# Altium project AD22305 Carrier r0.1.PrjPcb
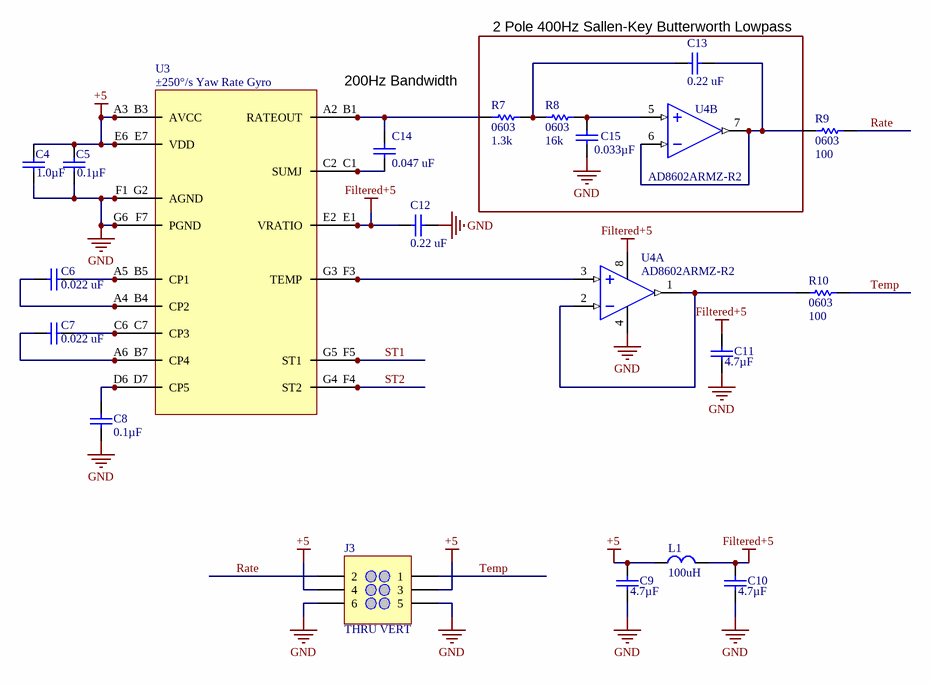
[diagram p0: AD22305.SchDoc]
ProjectTitle: AD22305 Carrier r0.1
2 sheets, 20 parts. Net scope: global (net labels, ports and power ports of the same name join across sheets).
Board file: AD22305 Carrier.PcbDoc
Sheets:
  AD22305.SchDoc
  Title.SchDoc

## Sheet AD22305.SchDoc
size Letter; SheetNumber: 2; SheetTotal: 2

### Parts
C4  value 1.0µF  [C0805_C]  (hidden comment: 1.0 uF 0805  25V)
C5  value 0.1µF  [C0805_C]  (hidden comment: 0.1uF 0805 Bypass)
C6  value 0.022 uF  [C0603_C]  (hidden comment: 0.022 uF 0603)
C7  value 0.022 uF  [C0603_C]  (hidden comment: 0.022 uF 0603)
C8  value 0.1µF  [C0805_C]  (hidden comment: 0.1uF 0805 Bypass)
C9  value 4.7µF  [C0805_C]  (hidden comment: 4.7uF 0805 25V X5R)
C10  value 4.7µF  [C0805_C]  (hidden comment: 4.7uF 0805 25V X5R)
C11  value 4.7µF  [C0805_C]  (hidden comment: 4.7uF 0805 25V X5R)
C12  value 0.22 uF  [C0603_C]  (hidden comment: 0.22 uF 0603)
C13  value 0.22 uF  [C0603_C]  (hidden comment: 0.22 uF 0603)
C14  value 0.047 uF  [C0603_C]  (hidden comment: 0.047uF 0603)
C15  value 0.033µF  [C0603_C]  (hidden comment: 0.022 uF 0603)
J3  THRU VERT  [H100P2x3 TSW-103-07-T-D]
L1  value 100uH  [L0805_C]  (hidden comment: 100 uH)
R7  value 1.3k  Footprint: 0603  [R0603_C]  (hidden comment: 1.3k ohm 0603 1%)
R8  value 16k  Footprint: 0603  [R0603_C]  (hidden comment: 16k ohm 0603 1%)
R9  value 100  Footprint: 0603  [R0603_C]  (hidden comment: 100 ohm 0603 1%)
R10  value 100  Footprint: 0603  [R0603_C]  (hidden comment: 100 ohm 0603 1%)
U3  ±250°/s Yaw Rate Gyro  [BC-32]
U4  MFG_PN: AD8602ARMZ-R2  [RM-8]  (hidden comment: AD8602 TSSOP)  (parts A,B of 2)

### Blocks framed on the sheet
2 Pole 400Hz Sallen-Key Butterworth Lowpass: C13 C15 R7 R8 U4

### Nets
+5: C4.2 C5.2 C9.2 J3.3 J3.4 L1.1 U3.A3(AVCC) U3.B3(AVCC) U3.E6(VDD) U3.E7(VDD)
Filtered+5: C10.2 C11.2 C12.2 L1.2 U3.E1(VRATIO) U3.E2(VRATIO) U4.8(+V)
GND: C4.1 C5.1 C8.1 C9.1 C10.1 C11.1 C12.1 C15.1 J3.5 J3.6 U3.F1(AGND) U3.F7(PGND) U3.G2(AGND) U3.G6(PGND) U4.4(-V)
Rate: J3.2 R9.2
ST1: U3.F5(ST1) U3.G5(ST1)
ST2: U3.F4(ST2) U3.G4(ST2)
Temp: J3.1 R10.2
NetC6_1: C6.1 U3.A4(CP2) U3.B4(CP2)
NetC6_2: C6.2 U3.A5(CP1) U3.B5(CP1)
NetC7_1: C7.1 U3.A6(CP4) U3.B7(CP4)
NetC7_2: C7.2 U3.C6(CP3) U3.C7(CP3)
NetC8_2: C8.2 U3.D6(CP5) U3.D7(CP5)
NetC13_1: C13.1 R9.1 U4.6(-IN_B) U4.7(OUT_B)
NetC13_2: C13.2 R7.2 R8.1
NetC14_1: C14.1 U3.C1(SUMJ) U3.C2(SUMJ)
NetC14_2: C14.2 R7.1 U3.A2(RATEOUT) U3.B1(RATEOUT)
NetC15_2: C15.2 R8.2 U4.5(+IN_B)
NetR10_1: R10.1 U4.1(OUT_A) U4.2(-IN_A)
NetU3_F3: U3.F3(TEMP) U3.G3(TEMP) U4.3(+IN_A)

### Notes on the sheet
- 200Hz Bandwidth

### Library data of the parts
C4 = 1.0 uF 0805  25V: MFG: Panasonic - ECG; MFG_PN: ECJ-2FB1E105K; DIST: DigiKey; DIST_PN: PCC2319CT-ND; Tolerance: ±10%; Temperature Coefficient: X5R; Voltage: 25
C5 C8 = 0.1uF 0805 Bypass: MFG: Kemet; MFG_PN: C0805C104K5RACTU; DIST: DigiKey; DIST_PN: 399-1170-1-ND; Tolerance: ±10%; Temperature Coefficient: X7R; Voltage: 50; Checked: SCH 3/2/2008; Cost (1000): 0.01260
C6 C7 = 0.022 uF 0603 50V: MFG: Panasonic - ECG; MFG_PN: ECJ-1VB1H223K; DIST: DigiKey; DIST_PN: PCC2282CT-ND; Tolerance: ±10%; Temperature Coefficient: X7R; Voltage: 50
C9-C11 = 4.7uF 0805 25V X5R: CERAMIC 4.7uF 25V X5R 0805; MFG: Panasonic - ECG; MFG_PN: ECJ-2FB1E475M; DIST: DigiKey; DIST_PN: PCC2321CT-ND; Tolerance: ±20%; Voltage: 25; Checked: SCH 3/2/2008; Cost (1000): 0.08988
C12 C13 = 0.22 uF 0603 10V: Capacitor; MFG: Panasonic - ECG; MFG_PN: ECJ-1VB1A224K; DIST: DigiKey; DIST_PN: PCC1749CT-ND; Tolerance: 10%; Temperature Coefficient: X5R; Voltage: 10
C14 = 0.047 uF 0603 50V: Capacitor; MFG: Panasonic - ECG; MFG_PN: ECJ-1VF1H473Z; DIST: DigiKey; DIST_PN: PCC1805CT-ND; Tolerance: -20%, +80%; Temperature Coefficient: Y5V (F); Voltage: 50
C15 = 0.033µF 0603 25V: MFG: Murata Electronics North America; MFG_PN: GRM188R71E333KA01D; DIST: DigiKey; DIST_PN: 490-1521-1-ND; Tolerance: ±10%; Temperature Coefficient: X7R; Voltage: 25; Cost (1000): 0.01300; Cost (MOQ): 0.05500
J3 = H100 2x3 THRU VERT: 2x3 Bird Pins; DIST: Samtec; DIST_PN: TSW-103-07-T-D; Cost (1000): 0.188; Cost (MOQ): 0.220; BOM Note: Generic
L1 = 100 uH 0805: MFG: Taiyo Yuden; MFG_PN: LBR2012T101K; DIST: DigiKey; DIST_PN: 587-2048-1-ND; Tol: 10%; Current Max: 0.050; Cost (1000): 0.06250
R7 = 1.3k ohm 0603 1%: MFG: Rohm; MFG_PN: MCR03EZPFX1301; DIST: DigiKey; DIST_PN: RHM1.30KHCT-ND; Power: 0.1; Cost (1000): 0.01595; Cost (MOQ): 0.076; BOM Note: Generic - May be replaced by equal or better part
R8 = 16k ohm 0603 1%: MFG: Rohm; MFG_PN: MCR03EZPFX1602; DIST: DigiKey; DIST_PN: RHM16.0KHCT-ND; Power: 0.1; Cost (1000): 0.01595; Cost (MOQ): 0.076; BOM Note: Generic - May be replaced by equal or better part
R9 R10 = 100 ohm 0603 1%: MFG: Rohm; MFG_PN: MCR03EZPFX1000; DIST: DigiKey; DIST_PN: RHM100HCT-ND; Power: 0.1; Cost (1000): 0.01595; Cost (MOQ): 0.076; BOM Note: Generic - May be replaced by equal or better part
U3 = AD22305: Supply Voltage Range: 4.85 - 5.15
U4 = AD8602 TSSOP: Op Amp 2x 8MHz Rail to Rail; DIST: DigiKey; DIST_PN: AD8602ARMZ-R2CT-ND; Maximum Output Current: 0.050; MFG: Analog Devices Inc; Noise, nV/rt(Hz): 8; Offset Voltage, Max (mV): 6; Offset Voltage, Nom (mV): 1.1; Cost (MOQ): 2.28000; Cost (1000): 1.36500

## Sheet Title.SchDoc
size Letter; SheetNumber: 0; SheetTotal: 2
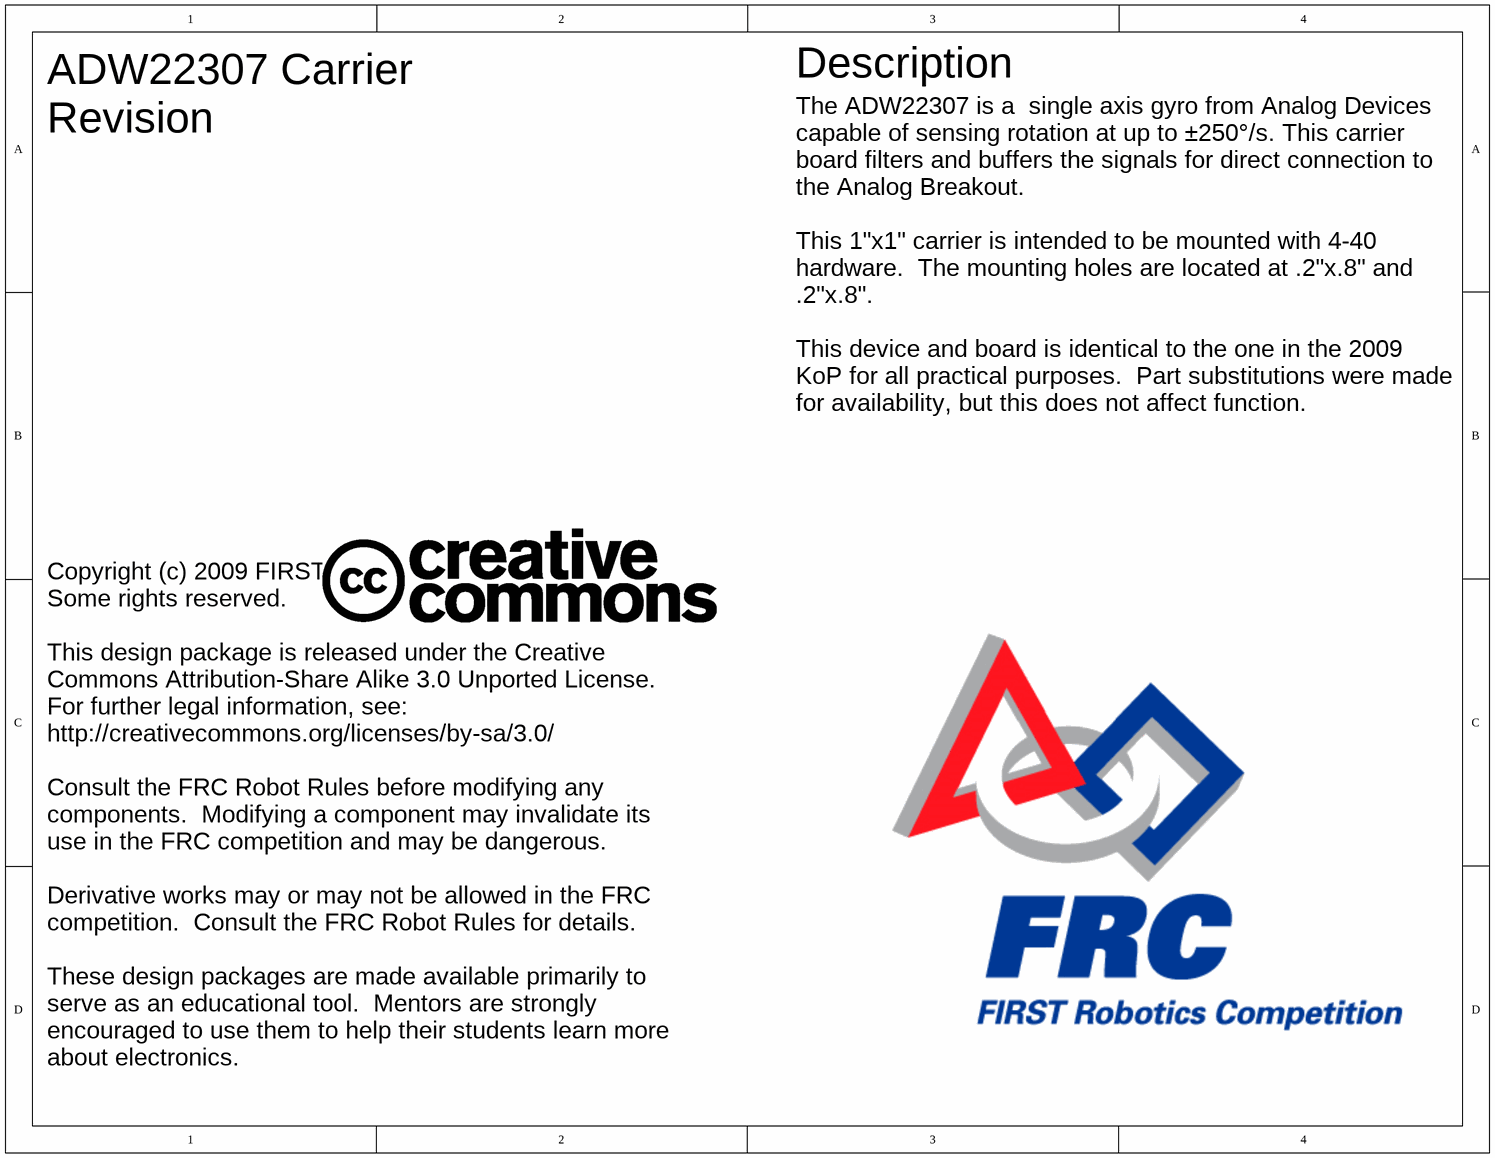
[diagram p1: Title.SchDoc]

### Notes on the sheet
- Description
- ADW22307 Carrier
  Revision
- The ADW22307 is a  single axis gyro from Analog Devices capable of sensing rotation at up to ±250°/s. This carrier board filters and buffers the signals for direct connection to the Analog Breakout.
  This 1"x1" carrier is intended to be mounted with 4-40 hardware.  The mounting holes are located at .2"x.8" and .2"x.8".
  This device and board is identical to the one in the 2009 KoP for all practical purposes.  Part substitutions were made for availability, but this does not affect function.
- Copyright (c) 2009 FIRST
  Some rights reserved.
  This design package is released under the Creative Commons Attribution-Share Alike 3.0 Unported License.  For further legal information, see:
  http://creativecommons.org/licenses/by-sa/3.0/
  Consult the FRC Robot Rules before modifying any components.  Modifying a component may invalidate its use in the FRC competition and may be dangerous.
  Derivative works may or may not be allowed in the FRC competition.  Consult the FRC Robot Rules for details.
  These design packages are made available primarily to serve as an educational tool.  Mentors are strongly encouraged to use them to help their students learn more about electronics.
